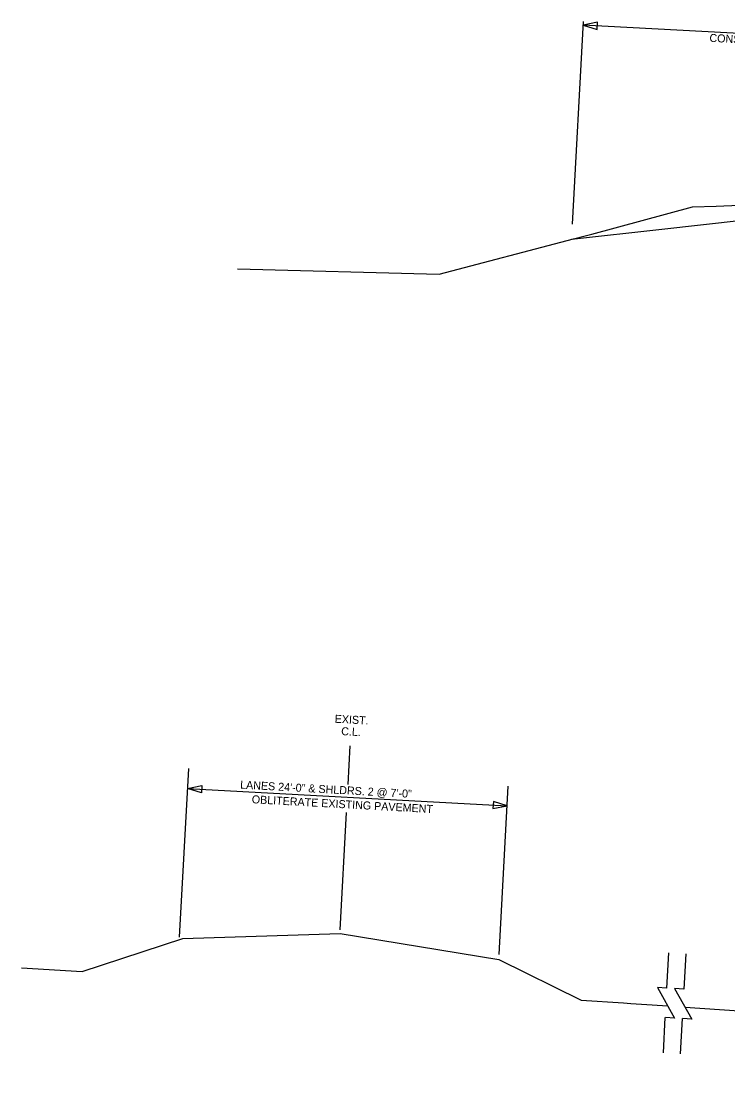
# Model space of a CAD drawing. Extents: x 879481 to 881064, y 1566477 to 1567504.
# Drawn here: x 879481 to 880010, y 1566660 to 1567467 of the extents above; entities that cross this region are included whole.
import ezdxf

# ---------------------------------------------------------------- set-up
doc = ezdxf.new("R2010")
doc.units = 0
for name, color, linetype in [('R_Border', 7, 'Continuous'), ('R_Border Prem', 7, 'Continuous'), ('R_Dimension', 7, 'Continuous'), ('R_Exist Surface', 7, 'Continuous'), ('R_Horz Alg', 7, 'Continuous'), ('R_Sheet Text', 7, 'Continuous')]:
    doc.layers.add(name, color=color, linetype=linetype)

msp = doc.modelspace()

# ---------------------------------------------------------------- linework, layer by layer
at = {"layer": 'R_Border Prem'}
for p, q in [((879965.67, 1566768.64), (879964.23, 1566742.25)), ((879978.58, 1566767.94), (879977.13, 1566741.55)), ((879978.58, 1566767.94), (879977.13, 1566741.55)), ((879964.23, 1566742.25), (879957.32, 1566742.63)), ((879957.32, 1566742.63), (879970.26, 1566719.75)), ((879977.13, 1566741.55), (879970.22, 1566741.92)), ((879970.22, 1566741.92), (879983.16, 1566719.05)), ((879977.13, 1566741.55), (879970.22, 1566741.92)), ((879970.22, 1566741.92), (879983.16, 1566719.05)), ((879963.03, 1566720.15), (879961.58, 1566693.75)), ((879970.26, 1566719.75), (879963.34, 1566720.13)), ((879975.93, 1566719.44), (879974.49, 1566693.05)), ((879975.93, 1566719.44), (879974.49, 1566693.05)), ((879983.16, 1566719.05), (879976.24, 1566719.43)), ((879983.16, 1566719.05), (879976.24, 1566719.43))]:
    msp.add_line(p, q, dxfattribs=at)
at = {"layer": 'R_Dimension'}
for p, q in [((879893.63, 1567314.61), (879901.89, 1567466.57)), ((880190.07, 1567448.25), (879901.75, 1567463.93)), ((879599.09, 1566780.42), (879605.96, 1566906.71)), ((879605.16, 1566891.89), (879844.8, 1566878.86)), ((879838.74, 1566767.38), (879845.61, 1566893.68))]:
    msp.add_line(p, q, dxfattribs=at)
for points in [[(879912.44, 1567465.99), (879901.75, 1567463.93), (879912.15, 1567460.72)], [(879615.56, 1566888.68), (879605.16, 1566891.89), (879615.84, 1566893.95)], [(879834.11, 1566876.79), (879844.8, 1566878.86), (879834.4, 1566882.07)]]:
    msp.add_lwpolyline(points, close=True, dxfattribs=at)
at = {"layer": 'R_Exist Surface'}
for points in [[(879642.65, 1567281.34), (879793.68, 1567277.22), (879894.46, 1567303.64), (879902.21, 1567305.66), (879908.13, 1567307.22), (879983.66, 1567327.64), (880001.33, 1567328.31), (880030.58, 1567329.55), (880034.41, 1567329.79), (880049.9, 1567331.77), (880066.74, 1567331.06)], [(879480.64, 1566757.44), (879526.22, 1566754.8), (879601.57, 1566779.33), (879719.42, 1566783.23), (879838.61, 1566763.7), (879900.2, 1566733.12), (879931.98, 1566731.1), (879937.42, 1566730.76), (879945.42, 1566730.22), (879965.09, 1566728.88)], [(879978.1, 1566727.99), (880353.48, 1566702.47), (880700.59, 1566679.09), (880767.22, 1566674.46), (880835.78, 1566669.89), (880991.43, 1566659.54)]]:
    msp.add_lwpolyline(points, dxfattribs=at)
at = {"layer": 'R_Horz Alg'}
for p, q in [((879725.49, 1566894.86), (879727.07, 1566923.82)), ((879719.57, 1566785.86), (879724.36, 1566873.93))]:
    msp.add_line(p, q, dxfattribs=at)
at = {"layer": 'R_Sheet Text'}
msp.add_lwpolyline([(880021.01, 1567317.51), (879960.57, 1567310.78), (879893.01, 1567303.26)], dxfattribs=at)

# ---------------------------------------------------------------- texts
at = {"layer": 'R_Border'}
for s, p in [('CONSTRUCTION STAGE 2', (879996.27, 1567451.4)), ('EXIST.', (879715.32, 1566941.12)), ('C.L.', (879720.17, 1566931.85)), ('LANES 24\'-0" & SHLDRS. 2 @ 7\'-0"', (879644.42, 1566891.79)), ('OBLITERATE EXISTING PAVEMENT', (879653.14, 1566880.8))]:
    msp.add_text(s, height=6, rotation=356.8871, dxfattribs=at).set_placement(p)

doc.saveas('drawing.dxf')
